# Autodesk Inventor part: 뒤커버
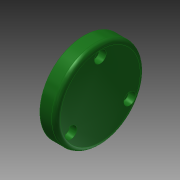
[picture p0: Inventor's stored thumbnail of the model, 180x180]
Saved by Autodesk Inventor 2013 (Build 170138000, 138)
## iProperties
Created: 2015-11
Part Number: 뒤커버
Material: 알루미늄 6061
Document SubType Name: Modeling
Designer: mduedu
Density: 1 g/cm^3
Author: mduedu
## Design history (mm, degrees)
sketch "스케치5"
  geometry: C1 r 30 at (0, 0); 2 further points
  constraints: 2 coincident, 1 centre point
  dimensions: "d66" = 60 diameter of C1
extrude "돌출2" new body sketch "스케치5" distance "d67" = 11; taper "d68" = 0 deg
sketch "스케치6"
  geometry: C1 r 16 at (0, 0); 1 further point
  constraints: 1 centre point, 1 coincident
  dimensions: "d69" = 32 diameter of C1
extrude "돌출3" join sketch "스케치6" distance "d70" = 3; taper "d71" = 0 deg
hole "구멍5" diameter "d74" = 27; stored, may be unused: countersink angle "d78" = 90 deg, drill point angle "d80" = 0 deg; dims "d75" = 6, "d76" = 4, "d77" = 2, "d79" = 10, "d100" = 10, "d101" = 10
fillet "모깎기8" dims "d82" = 3
fillet "모깎기9" dims "d83" = 3
fillet "모깎기10" dims "d84" = 0.3
sketch "스케치7" dims "d85" = 46
  geometry: 3 further points
  constraints: 2 vertical alignment, 1 coincident, 2 other
hole "구멍6" sketch "스케치7" at (0, 23) diameter "d86" = 4.5; stored, may be unused: countersink angle "d90" = 90 deg, drill point angle "d92" = 0 deg; dims "d87" = 6, "d88" = 8, "d89" = 4.6, "d91" = 10
node "솔리드2"
pattern_circular "원형 패턴3" dims angle "d94" = 360 deg
